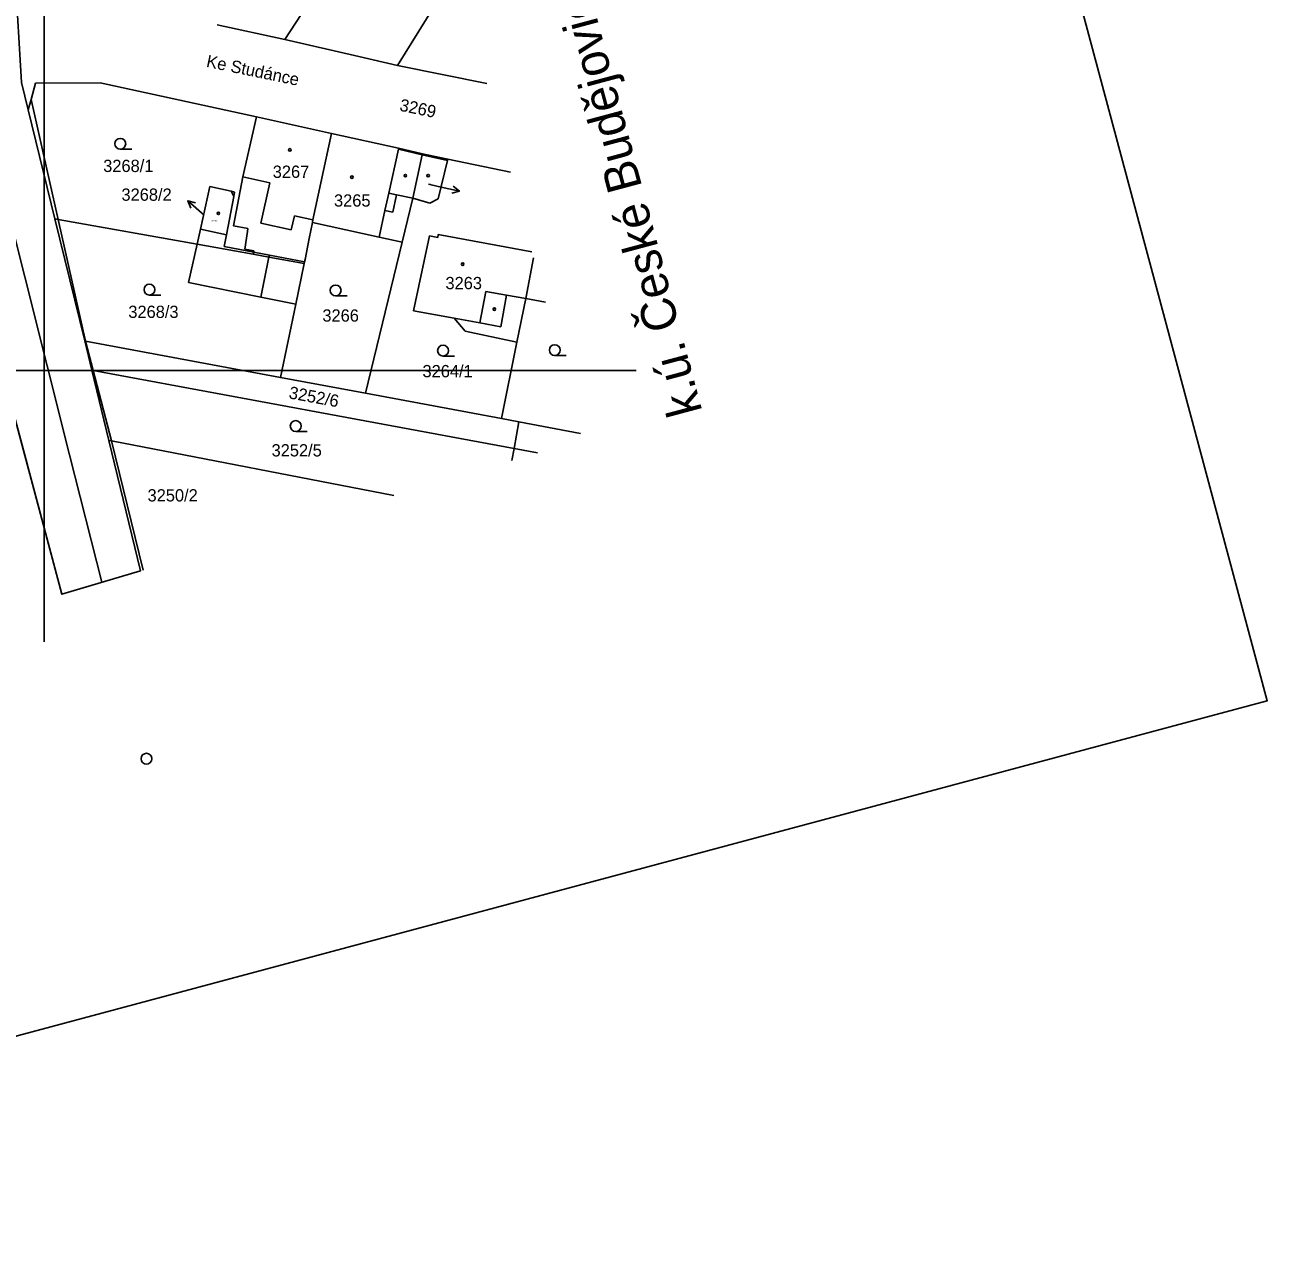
# Model space of a CAD drawing. Extents: x -754710 to -754206, y -1169123 to -1168234.
# Drawn here: x -754377.7 to -754205.7, y -1169122.6 to -1168952.2 of the extents above; entities that cross this region are included whole.
import ezdxf

# ---------------------------------------------------------------- set-up
doc = ezdxf.new("R2010")
doc.units = 0
for name, color, linetype in [('Vrstva 1', 7, 'Continuous'), ('Vrstva 15', 7, 'Continuous'), ('Vrstva 16', 7, 'Continuous'), ('Vrstva 18', 7, 'Continuous'), ('Vrstva 19', 7, 'Continuous'), ('Vrstva 24', 7, 'Continuous'), ('Vrstva 25', 7, 'Continuous'), ('Vrstva 3', 7, 'Continuous'), ('Vrstva 4', 7, 'Continuous'), ('Vrstva 6', 7, 'Continuous'), ('Vrstva 61', 7, 'Continuous')]:
    doc.layers.add(name, color=color, linetype=linetype)

msp = doc.modelspace()

# ---------------------------------------------------------------- linework, layer by layer
at = {"layer": 'Vrstva 1'}
for p, q in [((-754341.72, -1168954.18), (-754324.43, -1168927.54)), ((-754326.09, -1168957.79), (-754317.95, -1168944.62)), ((-754351.06, -1168952.16), (-754341.72, -1168954.18)), ((-754331.48, -1168956.55), (-754341.72, -1168954.18)), ((-754326.09, -1168957.79), (-754331.48, -1168956.55)), ((-754313.76, -1168960.27), (-754326.09, -1168957.79)), ((-754378.16, -1168960.13), (-754377.23, -1168963.95)), ((-754376.2, -1168960.23), (-754376.82, -1168962.5)), ((-754367.27, -1168960.2), (-754376.2, -1168960.23)), ((-754367.27, -1168960.2), (-754345.64, -1168964.92)), ((-754376.82, -1168962.5), (-754377.23, -1168963.95)), ((-754377.23, -1168963.95), (-754373.54, -1168979.01)), ((-754345.64, -1168964.92), (-754347.5, -1168973.21)), ((-754345.64, -1168964.92), (-754335.23, -1168967.19)), ((-754335.23, -1168967.19), (-754337.82, -1168979.18)), ((-754325.95, -1168969.24), (-754335.23, -1168967.19)), ((-754322.66, -1168970.03), (-754325.95, -1168969.24)), ((-754322.69, -1168970.17), (-754323.97, -1168976.18)), ((-754322.66, -1168970.03), (-754322.69, -1168970.17)), ((-754319.13, -1168970.76), (-754322.66, -1168970.03)), ((-754319.17, -1168970.96), (-754320.49, -1168976.26)), ((-754319.13, -1168970.76), (-754319.17, -1168970.96)), ((-754310.47, -1168972.56), (-754319.13, -1168970.76)), ((-754347.5, -1168973.21), (-754348.8, -1168980)), ((-754353.36, -1168980.47), (-754352.07, -1168974.56)), ((-754352.07, -1168974.56), (-754349.14, -1168975.2)), ((-754349.78, -1168981.25), (-754348.76, -1168975.91)), ((-754348.65, -1168975.31), (-754349.14, -1168975.2)), ((-754348.65, -1168975.31), (-754348.76, -1168975.91)), ((-754323.97, -1168976.18), (-754325.46, -1168982.26)), ((-754321.62, -1168976.87), (-754323.97, -1168976.18)), ((-754320.49, -1168976.26), (-754321.62, -1168976.87)), ((-754369.4, -1168995.91), (-754373.54, -1168979.01)), ((-754348.8, -1168980), (-754346.82, -1168980.37)), ((-754338.32, -1168981.76), (-754337.86, -1168979.53)), ((-754337.82, -1168979.18), (-754337.86, -1168979.53)), ((-754337.86, -1168979.53), (-754328.65, -1168981.56)), ((-754386.06, -1168980.52), (-754372.58, -1169030.98)), ((-754349.78, -1168981.25), (-754353.36, -1168980.47)), ((-754347.26, -1168983.23), (-754346.88, -1168980.76)), ((-754346.88, -1168980.76), (-754346.82, -1168980.37)), ((-754338.91, -1168984.63), (-754338.32, -1168981.76)), ((-754325.46, -1168982.26), (-754328.65, -1168981.56)), ((-754321.66, -1168981.38), (-754323.88, -1168991.76)), ((-754320.54, -1168981.59), (-754321.66, -1168981.38)), ((-754320.46, -1168981.2), (-754320.54, -1168981.59)), ((-754307.52, -1168983.57), (-754320.46, -1168981.2)), ((-754345.98, -1168983.45), (-754347.26, -1168983.23)), ((-754346.01, -1168983.62), (-754346.07, -1168983.93)), ((-754346.01, -1168983.62), (-754345.98, -1168983.45)), ((-754325.46, -1168982.26), (-754330.56, -1169003.14)), ((-754339.03, -1168985.19), (-754340.19, -1168990.83)), ((-754339.03, -1168985.19), (-754338.98, -1168984.96)), ((-754338.91, -1168984.63), (-754338.98, -1168984.96)), ((-754308.36, -1168990.05), (-754307.29, -1168984.42)), ((-754309.6, -1168996.07), (-754308.36, -1168990.05)), ((-754342.29, -1169000.96), (-754340.19, -1168990.83)), ((-754323.88, -1168991.76), (-754318.27, -1168992.78)), ((-754318.27, -1168992.78), (-754316.73, -1168994.57)), ((-754316.73, -1168994.57), (-754309.6, -1168996.07)), ((-754369.4, -1168995.91), (-754369.3, -1168995.93)), ((-754368.41, -1168999.96), (-754369.4, -1168995.91)), ((-754369.3, -1168995.93), (-754342.29, -1169000.96)), ((-754309.6, -1168996.07), (-754311.7, -1169006.65)), ((-754368.41, -1168999.96), (-754366.06, -1169009.68)), ((-754309.98, -1169010.8), (-754368.25, -1168999.99)), ((-754330.56, -1169003.14), (-754342.29, -1169000.96)), ((-754311.7, -1169006.65), (-754330.56, -1169003.14)), ((-754309.32, -1169007.1), (-754311.7, -1169006.65)), ((-754309.98, -1169010.8), (-754309.32, -1169007.1)), ((-754309.32, -1169007.1), (-754300.78, -1169008.71)), ((-754366.06, -1169009.68), (-754361.7, -1169027.75)), ((-754365.72, -1169009.75), (-754366.06, -1169009.68)), ((-754326.63, -1169017.31), (-754365.72, -1169009.75)), ((-754310.27, -1169012.45), (-754309.98, -1169010.8)), ((-754309.98, -1169010.8), (-754306.75, -1169011.4))]:
    msp.add_line(p, q, dxfattribs=at)
for points in [[(-754367.04, -1169029.33), (-754371.5, -1169011.68), (-754383.94, -1168962.43), (-754384.99, -1168958.29), (-754386.56, -1168952.08), (-754387.62, -1168947.84), (-754397.03, -1168910.64), (-754410.17, -1168858.68)], [(-754394.57, -1168948.26), (-754386.06, -1168980.52), (-754372.58, -1169030.98), (-754361.7, -1169027.75), (-754366.06, -1169009.68), (-754368.41, -1168999.96), (-754369.4, -1168995.91), (-754373.54, -1168979.01), (-754377.23, -1168963.95), (-754378.16, -1168960.13), (-754379.05, -1168945.33)]]:
    msp.add_lwpolyline(points, dxfattribs=at)
msp.add_circle((-754360.86, -1169053.75), 0.75, dxfattribs=at)
at = {"layer": 'Vrstva 16'}
for p, q in [((-754321.83, -1168974.24), (-754320.46, -1168974.54)), ((-754317.53, -1168975.18), (-754320.46, -1168974.54)), ((-754355.15, -1168976.52), (-754352.89, -1168978.49))]:
    msp.add_line(p, q, dxfattribs=at)
for points in [[(-754318.4, -1168974.48), (-754317.53, -1168975.18), (-754318.61, -1168975.46)], [(-754354.72, -1168977.55), (-754355.15, -1168976.52), (-754354.07, -1168976.8)]]:
    msp.add_lwpolyline(points, dxfattribs=at)
at = {"layer": 'Vrstva 25'}
for p, q in [((-754364.48, -1168969.38), (-754362.88, -1168969.38)), ((-754360.45, -1168989.57), (-754358.85, -1168989.57)), ((-754334.68, -1168989.68), (-754333.08, -1168989.68)), ((-754319.8, -1168998.01), (-754318.2, -1168998.01)), ((-754304.34, -1168997.94), (-754302.74, -1168997.94)), ((-754340.2, -1169008.45), (-754338.6, -1169008.45))]:
    msp.add_line(p, q, dxfattribs=at)
for centre, radius in [((-754364.48, -1168968.63), 0.75), ((-754341.01, -1168969.48), 0.175), ((-754332.42, -1168973.25), 0.175), ((-754325.02, -1168973.05), 0.175), ((-754321.87, -1168973.05), 0.175), ((-754350.91, -1168978.25), 0.175), ((-754317.08, -1168985.29), 0.175), ((-754360.45, -1168988.82), 0.75), ((-754334.68, -1168988.93), 0.75), ((-754312.7, -1168991.52), 0.175), ((-754319.8, -1168997.26), 0.75), ((-754304.34, -1168997.19), 0.75), ((-754340.2, -1169007.7), 0.75)]:
    msp.add_circle(centre, radius, dxfattribs=at)
at = {"layer": 'Vrstva 3'}
msp.add_lwpolyline([(-754710.01, -1168311.22), (-754492.6, -1169122.6), (-754205.72, -1169045.73), (-754423.13, -1168234.35)], close=True, dxfattribs=at)
for points in [[(-754375, -1168707.79), (-754375, -1169000), (-754517.39, -1169000)], [(-754375, -1169037.59), (-754375, -1169000), (-754293.08, -1169000)]]:
    msp.add_lwpolyline(points, dxfattribs=at)
at = {"layer": 'Vrstva 4'}
for p, q in [((-754373.09, -1168979.09), (-754376.82, -1168962.5)), ((-754327.31, -1168975.45), (-754325.98, -1168969.38)), ((-754325.98, -1168969.38), (-754325.95, -1168969.24)), ((-754325.98, -1168969.38), (-754322.69, -1168970.17)), ((-754322.69, -1168970.17), (-754319.17, -1168970.96)), ((-754347.5, -1168973.21), (-754343.76, -1168974.05)), ((-754343.76, -1168974.05), (-754345.01, -1168979.62)), ((-754349.14, -1168975.2), (-754348.76, -1168975.91)), ((-754327.31, -1168975.45), (-754327.84, -1168977.87)), ((-754326.24, -1168975.68), (-754327.31, -1168975.45)), ((-754326.24, -1168975.68), (-754326.77, -1168978.11)), ((-754323.97, -1168976.18), (-754326.24, -1168975.68)), ((-754327.84, -1168977.87), (-754328.65, -1168981.56)), ((-754326.77, -1168978.11), (-754327.84, -1168977.87)), ((-754369.3, -1168995.93), (-754373.09, -1168979.09)), ((-754345.01, -1168979.62), (-754340.82, -1168980.56)), ((-754340.82, -1168980.56), (-754340.38, -1168978.61)), ((-754340.38, -1168978.61), (-754337.82, -1168979.18)), ((-754353.36, -1168980.47), (-754353.83, -1168982.54)), ((-754349.78, -1168981.25), (-754350.09, -1168982.83)), ((-754353.83, -1168982.54), (-754355.02, -1168987.85)), ((-754350.09, -1168982.83), (-754346.01, -1168983.62)), ((-754343.84, -1168984.04), (-754346.01, -1168983.62)), ((-754345.04, -1168989.86), (-754343.9, -1168984.32)), ((-754343.84, -1168984.04), (-754343.9, -1168984.32)), ((-754343.84, -1168984.04), (-754338.98, -1168984.96)), ((-754355.02, -1168987.85), (-754345.04, -1168989.86)), ((-754345.04, -1168989.86), (-754340.19, -1168990.83)), ((-754313.9, -1168989.06), (-754314.69, -1168993.43)), ((-754311.03, -1168989.57), (-754313.9, -1168989.06)), ((-754311.03, -1168989.57), (-754311.82, -1168993.95)), ((-754308.36, -1168990.05), (-754311.03, -1168989.57)), ((-754308.36, -1168990.05), (-754305.64, -1168990.57)), ((-754314.69, -1168993.43), (-754318.27, -1168992.78)), ((-754311.82, -1168993.95), (-754314.69, -1168993.43)), ((-754368.25, -1168999.99), (-754369.3, -1168995.93)), ((-754368.25, -1168999.99), (-754365.72, -1169009.75)), ((-754361.31, -1169027.63), (-754365.72, -1169009.75))]:
    msp.add_line(p, q, dxfattribs=at)
at = {"layer": 'Vrstva 6'}
for p, q in [((-754373.54, -1168979.01), (-754373.09, -1168979.09)), ((-754373.09, -1168979.09), (-754353.83, -1168982.54)), ((-754346.07, -1168983.93), (-754353.83, -1168982.54)), ((-754346.07, -1168983.93), (-754343.9, -1168984.32)), ((-754343.9, -1168984.32), (-754339.03, -1168985.19)), ((-754368.41, -1168999.96), (-754368.25, -1168999.99))]:
    msp.add_line(p, q, dxfattribs=at)
at = {"layer": 'Vrstva 61'}
msp.add_lwpolyline([(-754492.6, -1169122.6), (-754205.72, -1169045.73), (-754423.13, -1168234.35), (-754710.01, -1168311.22)], dxfattribs=at)

# ---------------------------------------------------------------- texts
at = {"layer": 'Vrstva 15'}
msp.add_text('Ke Studánce', height=1.7, rotation=348.301, dxfattribs=at).set_placement((-754352.67, -1168957.97))
at = {"layer": 'Vrstva 16'}
msp.add_text('3268/2', height=1.7, dxfattribs=at).set_placement((-754364.32, -1168976.52))
at = {"layer": 'Vrstva 18'}
for s, rotation, p in [('3269', 348.301, (-754325.92, -1168964.04)), ('3252/6', 349.5043, (-754341.24, -1169003.85))]:
    msp.add_text(s, height=1.7, rotation=rotation, dxfattribs=at).set_placement(p)
for s, p in [('3268/1', (-754366.85, -1168972.54)), ('3268/3', (-754363.37, -1168992.74)), ('3266', (-754336.51, -1168993.25)), ('3264/1', (-754322.65, -1169000.95)), ('3252/5', (-754343.54, -1169011.91)), ('3250/2', (-754360.71, -1169018.14))]:
    msp.add_text(s, height=1.7, dxfattribs=at).set_placement(p)
at = {"layer": 'Vrstva 19'}
for s, height, p in [('3267', 1.7, (-754343.38, -1168973.35)), ('3264/2', 0.1, (-754321.82, -1168974.24)), ('3265', 1.7, (-754334.9, -1168977.33)), ('3268/2', 0.2, (-754351.85, -1168979.37)), ('3263', 1.7, (-754319.47, -1168988.76))]:
    msp.add_text(s, height=height, dxfattribs=at).set_placement(p)
at = {"layer": 'Vrstva 24'}
msp.add_text('k.ú. České Budějovice 6', height=4.8, rotation=105, dxfattribs=at).set_placement((-754283.89, -1169005.64))

doc.saveas('drawing.dxf')
